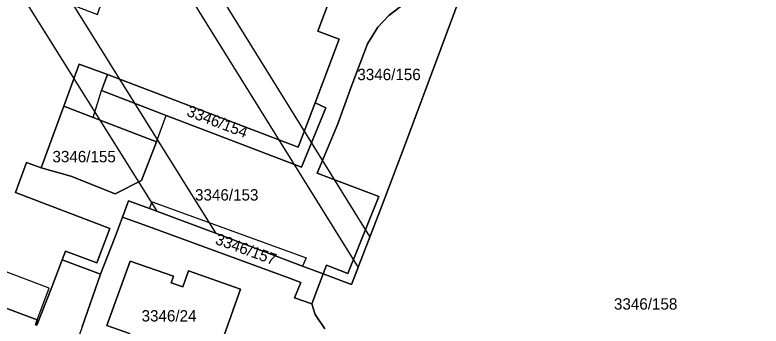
# Model space of a CAD drawing. Extents: x -262715 to -259381, y -1237238 to -1231182.
# Drawn here: x -262037.1 to -261905.8, y -1235502.6 to -1235447.9 of the extents above; entities that cross this region are included whole.
import ezdxf

# ---------------------------------------------------------------- set-up
doc = ezdxf.new("R2010")
doc.units = 0
for name, color, linetype in [('body_kn', 7, 'Continuous'), ('kladpar_druhypozemkov', 7, 'Continuous'), ('kladpar_hranice', 7, 'Continuous'), ('kladpar_parcelnecisla', 7, 'Continuous'), ('kladpar_plochy', 7, 'Continuous'), ('tarchy_linie', 7, 'Continuous'), ('zappar_hrandruhpozemk', 7, 'Continuous')]:
    doc.layers.add(name, color=color, linetype=linetype)

msp = doc.modelspace()

# ---------------------------------------------------------------- linework, layer by layer
at = {"layer": 'body_kn'}
for p, q in [((-261971.32, -1235447.97), (-261971.32, -1235447.97)), ((-261983.83, -1235450.76), (-261983.83, -1235450.76)), ((-261973.27, -1235450.01), (-261973.27, -1235450.01)), ((-261980.08, -1235452.15), (-261980.08, -1235452.15)), ((-261975.08, -1235452.97), (-261975.08, -1235452.97)), ((-261962.14, -1235453.82), (-261962.14, -1235453.82)), ((-262025.83, -1235456.55), (-262025.83, -1235456.55)), ((-262020.86, -1235458.38), (-262020.86, -1235458.38)), ((-262021.91, -1235461.18), (-262021.91, -1235461.18)), ((-261977.83, -1235460.23), (-261977.83, -1235460.23)), ((-262028.54, -1235463.9), (-262028.54, -1235463.9)), ((-262028.54, -1235463.9), (-262028.54, -1235463.9)), ((-261984.31, -1235463.35), (-261984.31, -1235463.35)), ((-261982.41, -1235464.19), (-261982.41, -1235464.19)), ((-262023.35, -1235465.91), (-262023.35, -1235465.91)), ((-262023.35, -1235465.91), (-262023.35, -1235465.91)), ((-262010.5, -1235465.54), (-262010.5, -1235465.54)), ((-261980.28, -1235467.05), (-261980.28, -1235467.05)), ((-262001.12, -1235469.11), (-262001.12, -1235469.11)), ((-262012.19, -1235470.21), (-262012.19, -1235470.21)), ((-262012.19, -1235470.21), (-262012.19, -1235470.21)), ((-261987.25, -1235471.14), (-261987.25, -1235471.14)), ((-261987.25, -1235471.14), (-261987.25, -1235471.14)), ((-261968.57, -1235470.95), (-261968.57, -1235470.95)), ((-262035.07, -1235473.81), (-262035.07, -1235473.81)), ((-261986.69, -1235474.66), (-261986.69, -1235474.66)), ((-262032.54, -1235474.76), (-262032.54, -1235474.76)), ((-261983.94, -1235475.71), (-261983.94, -1235475.71)), ((-262027.27, -1235476.25), (-262027.27, -1235476.25)), ((-262014.85, -1235476.99), (-262014.85, -1235476.99)), ((-262037.06, -1235479.11), (-262037.06, -1235479.11)), ((-262019.48, -1235479.34), (-262019.48, -1235479.34)), ((-261973.08, -1235479.83), (-261973.08, -1235479.83)), ((-261973.08, -1235479.83), (-261973.08, -1235479.83)), ((-262017.16, -1235480.54), (-262017.16, -1235480.54)), ((-262012.95, -1235480.72), (-262012.95, -1235480.72)), ((-262013.46, -1235481.92), (-262013.46, -1235481.92)), ((-262013.46, -1235481.92), (-262013.46, -1235481.92)), ((-262012.14, -1235482.41), (-262012.14, -1235482.41)), ((-261972.62, -1235481.61), (-261972.62, -1235481.61)), ((-262018.19, -1235483.44), (-262018.19, -1235483.44)), ((-262013.64, -1235485.1), (-262013.64, -1235485.1)), ((-262003.12, -1235484.3), (-262003.12, -1235484.3)), ((-262020.43, -1235485.46), (-262020.43, -1235485.46)), ((-262001.69, -1235486.32), (-262001.69, -1235486.32)), ((-262019.58, -1235487.22), (-262019.58, -1235487.22)), ((-262000.73, -1235486.68), (-262000.73, -1235486.68)), ((-261974.64, -1235486.87), (-261974.64, -1235486.87)), ((-262028.25, -1235489.41), (-262028.25, -1235489.41)), ((-262028.83, -1235490.94), (-262028.83, -1235490.94)), ((-262022.69, -1235491.5), (-262022.69, -1235491.5)), ((-262016.83, -1235491.16), (-262016.83, -1235491.16)), ((-261985.89, -1235490.58), (-261985.89, -1235490.58)), ((-262006.59, -1235492.85), (-262006.59, -1235492.85)), ((-261986.5, -1235492.04), (-261986.5, -1235492.04)), ((-261982.3, -1235491.91), (-261982.3, -1235491.91)), ((-261976.73, -1235492.29), (-261976.73, -1235492.29)), ((-261976.73, -1235492.29), (-261976.73, -1235492.29)), ((-262022.07, -1235493.48), (-262022.07, -1235493.48)), ((-262009.25, -1235493.81), (-262009.25, -1235493.81)), ((-261988.81, -1235494.19), (-261988.81, -1235494.19)), ((-261982.87, -1235493.41), (-261982.87, -1235493.41)), ((-261978.54, -1235493.36), (-261978.54, -1235493.36)), ((-262009.65, -1235494.97), (-262009.65, -1235494.97)), ((-261986.79, -1235494.93), (-261986.79, -1235494.93)), ((-261977.88, -1235495.29), (-261977.88, -1235495.29)), ((-262031.09, -1235495.9), (-262031.09, -1235495.9)), ((-262030.74, -1235496.03), (-262030.74, -1235496.03)), ((-262007.56, -1235495.68), (-262007.56, -1235495.68)), ((-261997.42, -1235496.12), (-261997.42, -1235496.12)), ((-261987.93, -1235497.65), (-261987.93, -1235497.65)), ((-261984.86, -1235498.7), (-261984.86, -1235498.7)), ((-261984.86, -1235498.7), (-261984.86, -1235498.7)), ((-261984.26, -1235500.55), (-261984.26, -1235500.55)), ((-262033.2, -1235501.52), (-262033.2, -1235501.52)), ((-262033.2, -1235501.52), (-262033.2, -1235501.52)), ((-262033.51, -1235502.35), (-262033.51, -1235502.35)), ((-262033.25, -1235502.45), (-262033.25, -1235502.45)), ((-262020.93, -1235502.47), (-262020.93, -1235502.47))]:
    msp.add_line(p, q, dxfattribs=at)
at = {"layer": 'kladpar_druhypozemkov'}
for p, q in [((-261970.65, -1235457.21), (-261970.65, -1235457.21)), ((-262008.61, -1235465.4), (-262008.61, -1235465.4)), ((-262024.28, -1235471.26), (-262024.28, -1235471.26)), ((-261999.34, -1235478.2), (-261999.34, -1235478.2)), ((-262009.99, -1235485.31), (-262009.99, -1235485.31)), ((-261926.24, -1235497.23), (-261926.24, -1235497.23)), ((-262008.61, -1235499.19), (-262008.61, -1235499.19))]:
    msp.add_line(p, q, dxfattribs=at)
at = {"layer": 'kladpar_hranice'}
for points in [[(-261982.61, -1235503.1), (-261984.26, -1235500.55), (-261984.86, -1235498.7), (-261982.87, -1235493.41), (-261977.88, -1235495.29), (-261972.62, -1235481.61), (-261968.57, -1235470.95), (-261962.14, -1235453.82), (-261956.24, -1235437.88), (-261946.68, -1235430.57), (-261947.51, -1235429.67), (-261945.29, -1235427.97), (-261941.07, -1235424.18), (-261937.44, -1235418.53), (-261930.24, -1235417.27), (-261912.18, -1235414.51), (-261898.94, -1235412.98)], [(-261973.08, -1235479.83), (-261983.94, -1235475.71), (-261980.28, -1235467.05), (-261977.83, -1235460.23), (-261975.08, -1235452.97), (-261973.27, -1235450.01), (-261971.32, -1235447.97), (-261962.36, -1235441.09), (-261953.96, -1235434.61), (-261947.51, -1235429.67), (-261946.68, -1235430.57), (-261956.24, -1235437.88), (-261962.14, -1235453.82), (-261968.57, -1235470.95), (-261972.62, -1235481.61), (-261977.88, -1235495.29), (-261982.87, -1235493.41), (-261982.3, -1235491.91), (-261978.54, -1235493.36), (-261973.08, -1235479.83)], [(-261962.36, -1235441.09), (-261971.32, -1235447.97), (-261973.27, -1235450.01), (-261975.08, -1235452.97), (-261977.83, -1235460.23), (-261980.28, -1235467.05), (-261983.94, -1235475.71), (-261973.08, -1235479.83), (-261978.54, -1235493.36), (-261982.3, -1235491.91), (-261982.87, -1235493.41), (-261986.5, -1235492.04), (-262000.73, -1235486.68), (-262013.46, -1235481.92), (-262017.16, -1235480.54), (-262018.19, -1235483.44), (-262019.58, -1235487.22), (-262022.07, -1235493.48), (-262028.83, -1235490.94), (-262028.25, -1235489.41), (-262022.69, -1235491.5), (-262020.43, -1235485.46), (-262037.06, -1235479.11), (-262035.07, -1235473.81), (-262032.54, -1235474.76), (-262027.27, -1235476.25), (-262019.48, -1235479.34), (-262014.85, -1235476.99), (-262012.19, -1235470.21), (-262023.35, -1235465.91), (-262028.54, -1235463.9), (-262025.83, -1235456.55), (-262020.86, -1235458.38), (-262021.91, -1235461.18), (-262010.5, -1235465.54), (-262001.12, -1235469.11), (-261986.69, -1235474.66), (-261982.41, -1235464.19), (-261984.31, -1235463.35), (-261980.08, -1235452.15), (-261983.83, -1235450.76), (-261981.67, -1235444.95)], [(-261981.67, -1235444.95), (-261983.83, -1235450.76), (-261980.08, -1235452.15), (-261984.31, -1235463.35), (-261987.25, -1235471.14), (-262020.86, -1235458.38), (-262025.83, -1235456.55), (-262028.54, -1235463.9), (-262032.54, -1235474.76), (-262035.07, -1235473.81), (-262037.06, -1235479.11), (-262020.43, -1235485.46), (-262022.69, -1235491.5), (-262028.25, -1235489.41), (-262028.83, -1235490.94), (-262030.74, -1235496.03), (-262033.25, -1235502.45), (-262033.51, -1235502.35), (-262033.2, -1235501.52), (-262041.28, -1235498.49)], [(-261987.25, -1235471.14), (-261984.31, -1235463.35), (-261982.41, -1235464.19), (-261986.69, -1235474.66), (-262001.12, -1235469.11), (-262010.5, -1235465.54), (-262021.91, -1235461.18), (-262020.86, -1235458.38), (-261987.25, -1235471.14)], [(-262028.54, -1235463.9), (-262023.35, -1235465.91), (-262012.19, -1235470.21), (-262014.85, -1235476.99), (-262019.48, -1235479.34), (-262027.27, -1235476.25), (-262032.54, -1235474.76), (-262028.54, -1235463.9)], [(-261984.86, -1235498.7), (-261987.93, -1235497.65), (-261986.79, -1235494.93), (-261988.81, -1235494.19), (-262013.64, -1235485.1), (-262018.19, -1235483.44), (-262017.16, -1235480.54), (-262013.46, -1235481.92), (-262000.73, -1235486.68), (-261986.5, -1235492.04), (-261982.87, -1235493.41), (-261984.86, -1235498.7)], [(-262025.28, -1235502.71), (-262022.07, -1235493.48), (-262019.58, -1235487.22), (-262018.19, -1235483.44), (-262013.64, -1235485.1), (-261988.81, -1235494.19), (-261986.79, -1235494.93), (-261987.93, -1235497.65), (-261984.86, -1235498.7), (-261984.26, -1235500.55), (-261982.61, -1235503.1)], [(-262041.28, -1235498.49), (-262033.2, -1235501.52), (-262033.51, -1235502.35), (-262033.25, -1235502.45), (-262030.74, -1235496.03), (-262028.83, -1235490.94), (-262022.07, -1235493.48), (-262025.28, -1235502.71), (-262028.18, -1235510.93), (-262049.19, -1235503.04)], [(-262037.64, -1235572.28), (-262035.59, -1235573.09), (-262036.67, -1235575.82), (-262027.45, -1235579.11), (-262021.39, -1235562.56), (-262003.31, -1235512.64), (-261997.42, -1235496.12), (-262006.59, -1235492.85), (-262007.56, -1235495.68), (-262009.65, -1235494.97), (-262009.25, -1235493.81), (-262016.83, -1235491.16), (-262020.93, -1235502.47), (-262016.96, -1235503.91), (-262017.6, -1235505.67), (-262011.72, -1235507.63)], [(-262012.32, -1235509.43), (-262011.72, -1235507.63), (-262017.6, -1235505.67), (-262016.96, -1235503.91), (-262020.93, -1235502.47), (-262016.83, -1235491.16), (-262009.25, -1235493.81), (-262009.65, -1235494.97), (-262007.56, -1235495.68), (-262006.59, -1235492.85), (-261997.42, -1235496.12), (-262003.31, -1235512.64), (-262012.32, -1235509.43)]]:
    msp.add_lwpolyline(points, dxfattribs=at)
at = {"layer": 'kladpar_plochy'}
for p, q in [((-262019.58, -1235487.22), (-262018.19, -1235483.44)), ((-262018.19, -1235483.44), (-262013.64, -1235485.1)), ((-262013.64, -1235485.1), (-261988.81, -1235494.19)), ((-262022.07, -1235493.48), (-262019.58, -1235487.22)), ((-262016.83, -1235491.16), (-262020.93, -1235502.47)), ((-262009.25, -1235493.81), (-262016.83, -1235491.16)), ((-262006.59, -1235492.85), (-262007.56, -1235495.68)), ((-261997.42, -1235496.12), (-262006.59, -1235492.85)), ((-262025.28, -1235502.71), (-262022.07, -1235493.48)), ((-262009.65, -1235494.97), (-262009.25, -1235493.81)), ((-261988.81, -1235494.19), (-261986.79, -1235494.93)), ((-262007.56, -1235495.68), (-262009.65, -1235494.97)), ((-261986.79, -1235494.93), (-261987.93, -1235497.65)), ((-262003.31, -1235512.64), (-261997.42, -1235496.12)), ((-261987.93, -1235497.65), (-261984.86, -1235498.7)), ((-261984.86, -1235498.7), (-261984.26, -1235500.55)), ((-261984.26, -1235500.55), (-261982.61, -1235503.1)), ((-262020.93, -1235502.47), (-262016.96, -1235503.91))]:
    msp.add_line(p, q, dxfattribs=at)
for points in [[(-261982.61, -1235503.1), (-261984.26, -1235500.55), (-261984.86, -1235498.7), (-261982.87, -1235493.41), (-261977.88, -1235495.29), (-261972.62, -1235481.61), (-261968.57, -1235470.95), (-261962.14, -1235453.82), (-261956.24, -1235437.88), (-261946.68, -1235430.57), (-261947.51, -1235429.67), (-261945.29, -1235427.97), (-261941.07, -1235424.18), (-261937.44, -1235418.53), (-261930.24, -1235417.27), (-261912.18, -1235414.51), (-261898.94, -1235412.98)], [(-261962.36, -1235441.09), (-261971.32, -1235447.97), (-261973.27, -1235450.01), (-261975.08, -1235452.97), (-261977.83, -1235460.23), (-261980.28, -1235467.05), (-261983.94, -1235475.71), (-261973.08, -1235479.83), (-261978.54, -1235493.36), (-261982.3, -1235491.91), (-261982.87, -1235493.41), (-261986.5, -1235492.04), (-262000.73, -1235486.68), (-262013.46, -1235481.92), (-262017.16, -1235480.54), (-262018.19, -1235483.44), (-262019.58, -1235487.22), (-262022.07, -1235493.48), (-262028.83, -1235490.94), (-262028.25, -1235489.41), (-262022.69, -1235491.5), (-262020.43, -1235485.46), (-262037.06, -1235479.11), (-262035.07, -1235473.81), (-262032.54, -1235474.76), (-262027.27, -1235476.25), (-262019.48, -1235479.34), (-262014.85, -1235476.99), (-262012.19, -1235470.21), (-262023.35, -1235465.91), (-262028.54, -1235463.9), (-262025.83, -1235456.55), (-262020.86, -1235458.38), (-262021.91, -1235461.18), (-262010.5, -1235465.54), (-262001.12, -1235469.11), (-261986.69, -1235474.66), (-261982.41, -1235464.19), (-261984.31, -1235463.35), (-261980.08, -1235452.15), (-261983.83, -1235450.76), (-261981.67, -1235444.95)], [(-261981.67, -1235444.95), (-261983.83, -1235450.76), (-261980.08, -1235452.15), (-261984.31, -1235463.35), (-261987.25, -1235471.14), (-262020.86, -1235458.38), (-262025.83, -1235456.55), (-262028.54, -1235463.9), (-262032.54, -1235474.76), (-262035.07, -1235473.81), (-262037.06, -1235479.11), (-262020.43, -1235485.46), (-262022.69, -1235491.5), (-262028.25, -1235489.41), (-262028.83, -1235490.94), (-262030.74, -1235496.03), (-262033.25, -1235502.45), (-262033.51, -1235502.35), (-262033.2, -1235501.52), (-262041.28, -1235498.49)], [(-262041.28, -1235498.49), (-262033.2, -1235501.52), (-262033.51, -1235502.35), (-262033.25, -1235502.45), (-262030.74, -1235496.03), (-262028.83, -1235490.94), (-262022.07, -1235493.48), (-262025.28, -1235502.71), (-262028.18, -1235510.93), (-262049.19, -1235503.04)]]:
    msp.add_lwpolyline(points, dxfattribs=at)
for points in [[(-261973.08, -1235479.83), (-261983.94, -1235475.71), (-261980.28, -1235467.05), (-261977.83, -1235460.23), (-261975.08, -1235452.97), (-261973.27, -1235450.01), (-261971.32, -1235447.97), (-261962.36, -1235441.09), (-261953.96, -1235434.61), (-261947.51, -1235429.67), (-261946.68, -1235430.57), (-261956.24, -1235437.88), (-261962.14, -1235453.82), (-261968.57, -1235470.95), (-261972.62, -1235481.61), (-261977.88, -1235495.29), (-261982.87, -1235493.41), (-261982.3, -1235491.91), (-261978.54, -1235493.36)], [(-261987.25, -1235471.14), (-261984.31, -1235463.35), (-261982.41, -1235464.19), (-261986.69, -1235474.66), (-262001.12, -1235469.11), (-262010.5, -1235465.54), (-262021.91, -1235461.18), (-262020.86, -1235458.38)], [(-262028.54, -1235463.9), (-262023.35, -1235465.91), (-262012.19, -1235470.21), (-262014.85, -1235476.99), (-262019.48, -1235479.34), (-262027.27, -1235476.25), (-262032.54, -1235474.76)], [(-261984.86, -1235498.7), (-261987.93, -1235497.65), (-261986.79, -1235494.93), (-261988.81, -1235494.19), (-262013.64, -1235485.1), (-262018.19, -1235483.44), (-262017.16, -1235480.54), (-262013.46, -1235481.92), (-262000.73, -1235486.68), (-261986.5, -1235492.04), (-261982.87, -1235493.41)], [(-262012.32, -1235509.43), (-262011.72, -1235507.63), (-262017.6, -1235505.67), (-262016.96, -1235503.91), (-262020.93, -1235502.47), (-262016.83, -1235491.16), (-262009.25, -1235493.81), (-262009.65, -1235494.97), (-262007.56, -1235495.68), (-262006.59, -1235492.85), (-261997.42, -1235496.12), (-262003.31, -1235512.64)]]:
    msp.add_lwpolyline(points, close=True, dxfattribs=at)
at = {"layer": 'tarchy_linie'}
for points in [[(-262079.16, -1235435.34), (-262076.34, -1235436.48), (-262073.46, -1235428.74), (-262037.21, -1235442.33), (-262012.14, -1235482.41), (-262013.46, -1235481.92), (-262017.16, -1235480.54), (-262018.19, -1235483.44), (-262019.58, -1235487.22), (-262022.07, -1235493.48), (-262025.28, -1235502.71), (-262028.18, -1235510.93), (-262045.96, -1235504.25), (-262092.46, -1235431.02), (-262086.55, -1235433.21), (-262081.62, -1235419.93), (-262076.17, -1235421.94), (-262077.63, -1235422.83), (-262080.31, -1235430.07), (-262080.52, -1235433.02), (-262079.16, -1235435.34)], [(-261976.73, -1235492.29), (-261977.88, -1235495.29), (-261982.87, -1235493.41), (-261986.5, -1235492.04), (-262000.73, -1235486.68), (-262001.69, -1235486.32), (-262026.76, -1235446.24), (-262022.62, -1235447.79), (-262022.22, -1235446.73), (-262016.51, -1235431.76), (-262015.91, -1235430.37), (-262015.04, -1235430.71), (-261976.73, -1235492.29)], [(-261956.24, -1235437.88), (-261962.14, -1235453.82), (-261968.57, -1235470.95), (-261972.62, -1235481.61), (-261974.64, -1235486.87), (-262007.78, -1235433.5)]]:
    msp.add_lwpolyline(points, dxfattribs=at)
at = {"layer": 'zappar_hrandruhpozemk'}
for p, q in [((-262023.35, -1235465.91), (-262021.91, -1235461.18)), ((-262012.19, -1235470.21), (-262010.5, -1235465.54)), ((-262003.12, -1235484.3), (-261985.89, -1235490.58)), ((-261985.89, -1235490.58), (-261986.5, -1235492.04)), ((-262031.09, -1235495.9), (-262039.17, -1235492.86)), ((-262033.2, -1235501.52), (-262031.09, -1235495.9))]:
    msp.add_line(p, q, dxfattribs=at)
msp.add_lwpolyline([(-262013.46, -1235481.92), (-262012.95, -1235480.72), (-262003.12, -1235484.3)], dxfattribs=at)

# ---------------------------------------------------------------- texts
at = {"layer": 'kladpar_parcelnecisla'}
for s, p in [('3346/156', (-261976.86, -1235459.35)), ('3346/155', (-262030.53, -1235473.79)), ('3346/153', (-262005.43, -1235480.52)), ('3346/158', (-261931.69, -1235499.7)), ('3346/24', (-262014.84, -1235501.79))]:
    msp.add_text(s, height=2, dxfattribs=at).set_placement(p)
for s, rotation, p in [('3346/154', 339, (-262007.04, -1235465.57)), ('3346/157', 340, (-262002.03, -1235488.1))]:
    msp.add_text(s, height=2, rotation=rotation, dxfattribs=at).set_placement(p)

doc.saveas('drawing.dxf')
